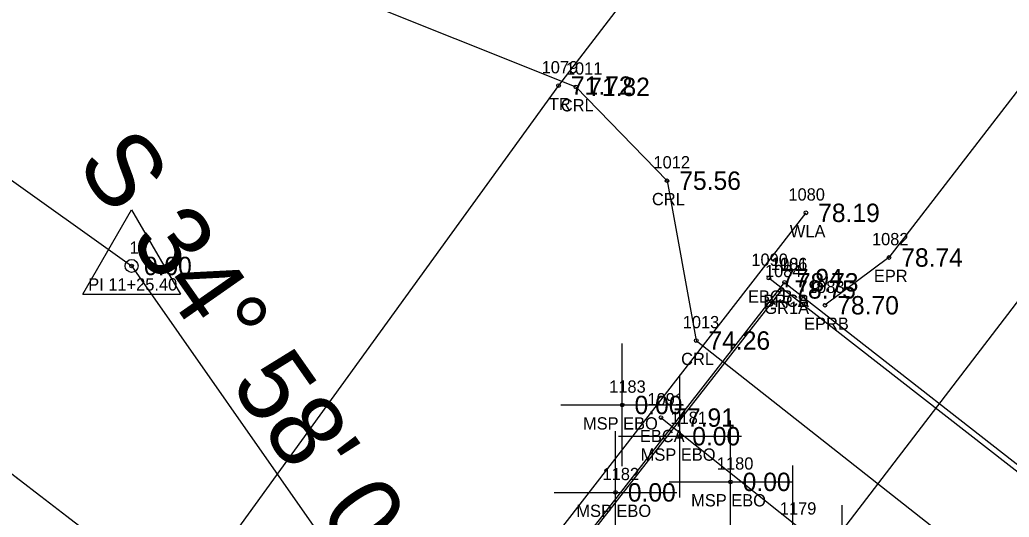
# Model space of a CAD drawing. Extents: x 2505249 to 2506333, y 912937 to 914171.
# Drawn here: x 2505748.6 to 2505829.2, y 913525.4 to 913565.9 of the extents above; entities that cross this region are included whole.
import ezdxf

# ---------------------------------------------------------------- set-up
doc = ezdxf.new("R2010")
doc.units = 0
for name, color, linetype in [('RD_EX_Bridge', 7, 'Continuous'), ('RD_EX_Bridge_txCode', 7, 'Continuous'), ('RD_EX_GuardRail', 7, 'Continuous'), ('RD_EX_GuardRail_txCode', 7, 'Continuous'), ('RD_EX_H2O', 7, 'Continuous'), ('RD_EX_H2O_txCode', 7, 'Continuous'), ('RD_EX_Misc', 7, 'Continuous'), ('RD_EX_Misc_txCode', 7, 'Continuous'), ('RD_EX_Road', 7, 'Continuous'), ('RD_EX_Road_txCode', 7, 'Continuous'), ('RD_EX_TX_Bridge_ELEV', 7, 'Continuous'), ('RD_EX_TX_GuardRail_ELEV', 7, 'Continuous'), ('RD_EX_TX_H2O_ELEV', 7, 'Continuous'), ('RD_EX_TX_Misc_ELEV', 7, 'Continuous'), ('RD_EX_TX_Road_ELEV', 7, 'Continuous'), ('RD_EX_TX_UT_ELEV', 7, 'Continuous'), ('RD_EX_TX_VEG_ELEV', 7, 'Continuous'), ('RD_EX_UT', 7, 'Continuous'), ('RD_EX_UT_txCode', 7, 'Continuous'), ('RD_EX_VEG', 7, 'Continuous'), ('RD_EX_VEG_txCode', 7, 'Continuous'), ('RD_HC_Cl', 7, 'Continuous'), ('RD_HC_Data', 7, 'Continuous'), ('RD_HC_Survey_ELEV', 7, 'Continuous'), ('RD_HC_txCode', 7, 'Continuous'), ('RD_SMD_Locator', 7, 'Continuous')]:
    doc.layers.add(name, color=color, linetype=linetype)

msp = doc.modelspace()

# ---------------------------------------------------------------- linework, layer by layer
at = {"layer": 'RD_EX_Bridge'}
for p, q in [((2505835.878, 913524.37), (2505809.62, 913544.857)), ((2505800.831, 913533.486), (2505826.933, 913512.731))]:
    msp.add_line(p, q, dxfattribs=at)
msp.add_lwpolyline([(2505810.902, 913544.512), (2505835.376, 913525.368), (2505780.208, 913454.04), (2505755.58, 913473.496), (2505810.902, 913544.512)], dxfattribs=at)
at = {"layer": 'RD_EX_GuardRail'}
msp.add_line((2505810.689, 913543.934), (2505755.898, 913473.882), dxfattribs=at)
at = {"layer": 'RD_EX_H2O'}
msp.add_lwpolyline([(2505762.262, 913658.109), (2505746.145, 913644.246), (2505726.467, 913615.205), (2505674.206, 913628.007), (2505666.247, 913620.583), (2505714.598, 913592.147), (2505793.902, 913560.447), (2505801.323, 913552.799), (2505803.704, 913539.769), (2505832.625, 913516.964), (2505848.424, 913517.193), (2505881.862, 913528.443), (2505910.198, 913538.779), (2505939.304, 913544.448), (2505946.254, 913542.537), (2505974.653, 913535.178), (2506004.111, 913524.704), (2506052.031, 913515.471), (2506115.491, 913494.68), (2506138.045, 913548.886)], dxfattribs=at)
at = {"layer": 'RD_EX_Misc'}
for p, q in [((2505797.675, 913529.515), (2505797.675, 913539.515)), ((2505802.378, 913526.971), (2505802.378, 913536.971)), ((2505792.675, 913534.515), (2505802.675, 913534.515)), ((2505806.486, 913523.247), (2505806.486, 913533.247)), ((2505797.132, 913522.39), (2505797.132, 913532.39)), ((2505797.378, 913531.971), (2505807.378, 913531.971)), ((2505811.577, 913519.584), (2505811.577, 913529.584)), ((2505801.486, 913528.247), (2505811.486, 913528.247)), ((2505792.132, 913527.39), (2505802.132, 913527.39)), ((2505815.584, 913516.355), (2505815.584, 913526.355))]:
    msp.add_line(p, q, dxfattribs=at)
at = {"layer": 'RD_EX_Road'}
msp.add_lwpolyline([(2506024.035, 913813.099), (2505962.007, 913732.059), (2505903.299, 913655.934), (2505840.875, 913574.403), (2505819.406, 913546.536), (2505814.194, 913542.643)], dxfattribs=at)
at = {"layer": 'RD_EX_UT'}
msp.add_line((2505812.637, 913550.177), (2505751.539, 913471.474), dxfattribs=at)
at = {"layer": 'RD_EX_VEG'}
msp.add_lwpolyline([(2506002.64, 913815.253), (2505883.703, 913669.642), (2505827.831, 913593.293), (2505814.43, 913589.154), (2505792.492, 913560.547), (2505725.635, 913468.235), (2505664.365, 913399.088), (2505478.329, 913221.003), (2505411.986, 913152.193), (2505339.126, 913074.528)], dxfattribs=at)
at = {"layer": 'RD_HC_Cl'}
for p, q in [((2505792.762, 913494.508), (2506032.344, 913807.095)), ((2505655.631, 913618.691), (2505757.703, 913545.846)), ((2505757.703, 913545.846), (2505780.822, 913512.79))]:
    msp.add_line(p, q, dxfattribs=at)
at = {"layer": 'RD_HC_Data'}
for p, q in [((2505792.762, 913494.508), (2505701.426, 913564.513)), ((2505753.732, 913543.553), (2505757.704, 913550.433)), ((2505757.704, 913550.433), (2505761.673, 913543.553)), ((2505753.732, 913543.553), (2505761.673, 913543.553))]:
    msp.add_line(p, q, dxfattribs=at)
msp.add_circle((2505757.703, 913545.846), 0.529, dxfattribs=at)
at = {"layer": 'RD_SMD_Locator'}
for centre in [(2505792.492, 913560.547), (2505793.902, 913560.447), (2505801.323, 913552.799), (2505812.637, 913550.177), (2505819.406, 913546.536), (2505757.703, 913545.846), (2505809.62, 913544.857), (2505810.902, 913544.512), (2505810.902, 913544.512), (2505810.689, 913543.934), (2505814.194, 913542.643), (2505803.704, 913539.769), (2505797.675, 913534.515), (2505800.831, 913533.486), (2505802.378, 913531.971), (2505806.486, 913528.247), (2505797.132, 913527.39)]:
    msp.add_circle(centre, 0.15, dxfattribs=at)

# ---------------------------------------------------------------- texts
at = {"layer": 'RD_EX_Bridge_txCode'}
for s, p in [('1090', (2505808.195, 913545.857)), ('1106', (2505809.776, 913545.512)), ('1081', (2505809.8, 913545.512)), ('EBCB', (2505807.92, 913542.857)), ('BRCA', (2505809.162, 913542.512)), ('BRCB', (2505809.178, 913542.512)), ('1091', (2505799.729, 913534.486)), ('EBCA', (2505799.114, 913531.486))]:
    msp.add_text(s, height=1, dxfattribs=at).set_placement(p)
at = {"layer": 'RD_EX_GuardRail_txCode'}
for s, p in [('1084', (2505809.303, 913544.934)), ('GR1A', (2505809.255, 913541.934))]:
    msp.add_text(s, height=1, dxfattribs=at).set_placement(p)
at = {"layer": 'RD_EX_H2O_txCode'}
for s, p in [('1011', (2505793.083, 913561.447)), ('CRL', (2505792.674, 913558.447)), ('1012', (2505800.22, 913553.799)), ('CRL', (2505800.094, 913550.799)), ('1013', (2505802.602, 913540.769)), ('CRL', (2505802.476, 913537.769))]:
    msp.add_text(s, height=1, dxfattribs=at).set_placement(p)
at = {"layer": 'RD_EX_Misc_txCode'}
for s, p in [('1183', (2505796.612, 913535.515)), ('1181', (2505801.599, 913532.971)), ('MSP EBO', (2505794.478, 913532.515)), ('MSP EBO', (2505799.181, 913529.971)), ('1180', (2505805.384, 913529.247)), ('1182', (2505796.07, 913528.39)), ('MSP EBO', (2505803.289, 913526.247)), ('MSP EBO', (2505793.936, 913525.39)), ('1179', (2505810.514, 913525.584))]:
    msp.add_text(s, height=1, dxfattribs=at).set_placement(p)
at = {"layer": 'RD_EX_Road_txCode'}
for s, p in [('1082', (2505818.02, 913547.536)), ('EPR', (2505818.177, 913544.536)), ('1083', (2505812.808, 913543.643)), ('EPRB', (2505812.493, 913540.643))]:
    msp.add_text(s, height=1, dxfattribs=at).set_placement(p)
at = {"layer": 'RD_EX_TX_Bridge_ELEV'}
for s, p in [('77.94', (2505810.62, 913544.107)), ('78.73', (2505811.902, 913543.762)), ('78.73', (2505811.902, 913543.762)), ('77.91', (2505801.831, 913532.736))]:
    msp.add_text(s, height=1.5, dxfattribs=at).set_placement(p)
at = {"layer": 'RD_EX_TX_GuardRail_ELEV'}
msp.add_text('78.75', height=1.5, dxfattribs=at).set_placement((2505811.689, 913543.184))
at = {"layer": 'RD_EX_TX_H2O_ELEV'}
for s, p in [('71.82', (2505794.902, 913559.697)), ('75.56', (2505802.323, 913552.049)), ('74.26', (2505804.704, 913539.019))]:
    msp.add_text(s, height=1.5, dxfattribs=at).set_placement(p)
at = {"layer": 'RD_EX_TX_Misc_ELEV'}
for p in [(2505798.675, 913533.765), (2505803.378, 913531.221), (2505807.486, 913527.497), (2505798.132, 913526.64)]:
    msp.add_text('0.00', height=1.5, dxfattribs=at).set_placement(p)
at = {"layer": 'RD_EX_TX_Road_ELEV'}
for s, p in [('78.74', (2505820.406, 913545.786)), ('78.70', (2505815.194, 913541.893))]:
    msp.add_text(s, height=1.5, dxfattribs=at).set_placement(p)
at = {"layer": 'RD_EX_TX_UT_ELEV'}
msp.add_text('78.19', height=1.5, dxfattribs=at).set_placement((2505813.637, 913549.427))
at = {"layer": 'RD_EX_TX_VEG_ELEV'}
msp.add_text('71.72', height=1.5, dxfattribs=at).set_placement((2505793.492, 913559.797))
at = {"layer": 'RD_EX_UT_txCode'}
for s, p in [('1080', (2505811.212, 913551.177)), ('WLA', (2505811.33, 913548.177))]:
    msp.add_text(s, height=1, dxfattribs=at).set_placement(p)
at = {"layer": 'RD_EX_VEG_txCode'}
for s, p in [('1079', (2505791.106, 913561.547)), ('TR', (2505791.697, 913558.547))]:
    msp.add_text(s, height=1, dxfattribs=at).set_placement(p)
at = {"layer": 'RD_HC_Data'}
msp.add_text('S 34%%d 58\' 09" E', height=6, rotation=304.96917, dxfattribs=at).set_placement((2505753.091, 913554.184))
at = {"layer": 'RD_HC_Survey_ELEV'}
msp.add_text('0.00', height=1.5, dxfattribs=at).set_placement((2505758.703, 913545.096))
at = {"layer": 'RD_HC_txCode'}
for s, p in [('11', (2505757.537, 913546.846)), ('PI 11+25.40', (2505754.167, 913543.846))]:
    msp.add_text(s, height=1, dxfattribs=at).set_placement(p)

doc.saveas('drawing.dxf')
